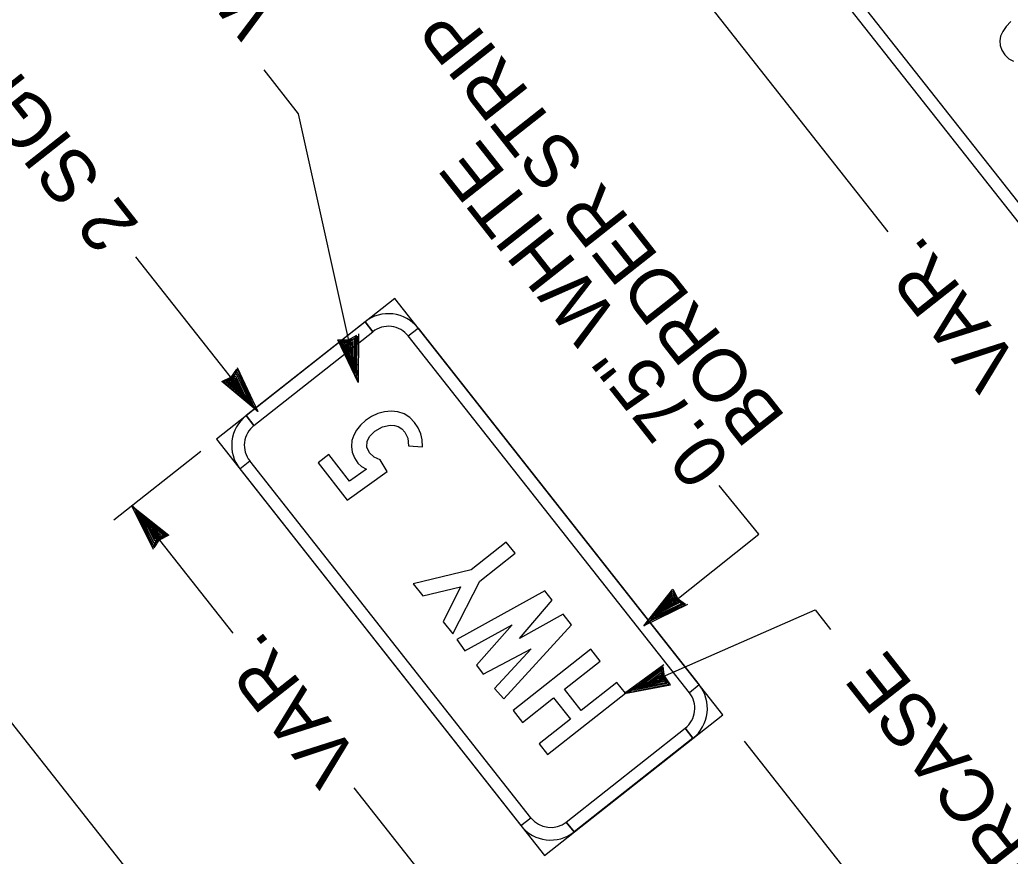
# Model space of a CAD drawing. Extents: x 672438 to 673980, y 1673259 to 1674850.
# Drawn here: x 673647.2 to 673725.7, y 1673361.1 to 1673427.3 of the extents above; entities that cross this region are included whole.
import ezdxf

# ---------------------------------------------------------------- set-up
doc = ezdxf.new("R2010")
doc.units = 0
for name, color, linetype in [('61', 7, 'Continuous'), ('C-ANNO-SYMB', 7, 'Continuous'), ('Level 1', 7, 'Continuous'), ('V-SIGNAL-LOOP', 7, 'Continuous')]:
    doc.layers.add(name, color=color, linetype=linetype)

msp = doc.modelspace()

# ---------------------------------------------------------------- linework, layer by layer
at = {"layer": '61'}
msp.add_lwpolyline([(673683.105, 1673325.233), (673609.575, 1673418.504), (673586.623, 1673400.409), (673660.153, 1673307.138)], close=True, dxfattribs=at)
at = {"layer": 'C-ANNO-SYMB'}
for p, q in [((673688.27, 1673459.545), (673766.277, 1673360.596)), ((673765.205, 1673363.571), (673690.913, 1673457.808)), ((673690.127, 1673457.189), (673764.42, 1673362.952)), ((673676.882, 1673405.27), (673662.746, 1673394.126)), ((673702.884, 1673372.287), (673676.882, 1673405.27)), ((673674.526, 1673403.412), (673665.102, 1673395.983)), ((673674.526, 1673403.412), (673675.145, 1673402.627)), ((673675.145, 1673402.627), (673674.526, 1673403.412)), ((673677.954, 1673402.295), (673678.739, 1673402.914)), ((673677.954, 1673402.295), (673678.739, 1673402.914)), ((673677.954, 1673402.295), (673678.739, 1673402.914)), ((673678.739, 1673402.914), (673701.027, 1673374.643)), ((673665.721, 1673395.198), (673675.145, 1673402.627)), ((673675.145, 1673402.627), (673675.145, 1673402.627)), ((673675.145, 1673402.627), (673675.145, 1673402.627)), ((673700.241, 1673374.024), (673677.954, 1673402.295)), ((673665.721, 1673395.198), (673665.102, 1673395.983)), ((673665.102, 1673395.983), (673665.721, 1673395.198)), ((673662.746, 1673394.126), (673688.748, 1673361.143)), ((673664.603, 1673391.77), (673665.389, 1673392.389)), ((673664.603, 1673391.77), (673665.389, 1673392.389)), ((673665.389, 1673392.389), (673665.389, 1673392.389)), ((673665.389, 1673392.389), (673665.389, 1673392.389)), ((673687.676, 1673364.118), (673665.389, 1673392.389)), ((673664.603, 1673391.77), (673686.891, 1673363.499)), ((673701.027, 1673374.643), (673700.241, 1673374.024)), ((673701.027, 1673374.643), (673700.241, 1673374.024)), ((673700.241, 1673374.024), (673700.241, 1673374.024)), ((673700.241, 1673374.024), (673700.241, 1673374.024)), ((673688.748, 1673361.143), (673702.884, 1673372.287)), ((673702.884, 1673372.287), (673702.884, 1673372.287)), ((673702.884, 1673372.287), (673702.884, 1673372.287)), ((673690.485, 1673363.785), (673699.909, 1673371.215)), ((673699.909, 1673371.215), (673700.528, 1673370.429)), ((673700.528, 1673370.429), (673699.909, 1673371.215)), ((673700.528, 1673370.429), (673691.104, 1673363)), ((673686.891, 1673363.499), (673687.676, 1673364.118)), ((673686.891, 1673363.499), (673687.676, 1673364.118)), ((673691.104, 1673363), (673690.485, 1673363.785)), ((673690.485, 1673363.785), (673690.485, 1673363.785)), ((673690.485, 1673363.785), (673690.485, 1673363.785)), ((673690.485, 1673363.785), (673691.104, 1673363)), ((673691.104, 1673363), (673690.485, 1673363.785))]:
    msp.add_line(p, q, dxfattribs=at)
msp.add_lwpolyline([(673725.719, 1673427.209), (673725.353, 1673426.814), (673725.09, 1673426.424), (673724.92, 1673426.041), (673724.856, 1673425.664), (673724.885, 1673425.293), (673725.017, 1673424.928), (673725.245, 1673424.572), (673725.566, 1673424.255), (673725.933, 1673424.059)], dxfattribs=at)
for points in [[(673679.091, 1673393.514), (673679.058, 1673394.053), (673678.94, 1673394.553), (673678.74, 1673395.015), (673678.458, 1673395.442), (673678.072, 1673395.841), (673677.633, 1673396.126), (673677.139, 1673396.293), (673676.587, 1673396.345), (673676.063, 1673396.296), (673675.551, 1673396.152), (673675.054, 1673395.917), (673674.566, 1673395.587), (673674.169, 1673395.228), (673673.854, 1673394.842), (673673.628, 1673394.434), (673673.487, 1673394.002), (673673.445, 1673393.535), (673673.507, 1673393.081), (673673.68, 1673392.636), (673673.958, 1673392.206), (673674.245, 1673391.943), (673674.644, 1673391.74), (673673.307, 1673390.795), (673671.65, 1673392.897), (673670.804, 1673392.23), (673673.117, 1673389.296), (673676.279, 1673391.547), (673675.717, 1673392.486), (673675.245, 1673392.694), (673674.875, 1673393.03), (673674.661, 1673393.48), (673674.697, 1673393.958), (673674.921, 1673394.367), (673675.299, 1673394.745), (673675.904, 1673395.102), (673676.525, 1673395.236), (673676.863, 1673395.213), (673677.167, 1673395.112), (673677.444, 1673394.936), (673677.686, 1673394.683), (673677.931, 1673394.196), (673677.984, 1673393.598)], [(673679.102, 1673381.704), (673682.102, 1673382.407), (673680.735, 1673379.633), (673681.479, 1673378.689), (673683.639, 1673382.881), (673686.43, 1673385.081), (673685.73, 1673385.97), (673682.938, 1673383.769), (673678.343, 1673382.667)], [(673690.894, 1673379.42), (673690.245, 1673380.243), (673686.775, 1673378.328), (673689.37, 1673381.353), (673688.77, 1673382.114), (673681.818, 1673378.259), (673682.452, 1673377.351), (673686.194, 1673379.413), (673683.354, 1673376.207), (673683.902, 1673375.512), (673687.698, 1673377.507), (673684.799, 1673374.374), (673685.54, 1673373.538)], [(673695.168, 1673373.997), (673694.502, 1673374.842), (673691.675, 1673372.613), (673690.341, 1673374.305), (673693.168, 1673376.534), (673692.426, 1673377.476), (673686.265, 1673372.619), (673687.007, 1673371.677), (673689.478, 1673373.625), (673690.812, 1673371.933), (673688.341, 1673369.985), (673689.007, 1673369.14)]]:
    msp.add_lwpolyline(points, close=True, dxfattribs=at)
for centre, radius, start, end in [((673676.383, 1673401.057), 3, 38.2506, 128.25081), ((673676.383, 1673401.057), 2, 38.2506, 128.25081), ((673666.959, 1673393.627), 3, 128.25054, 218.25075), ((673666.959, 1673393.627), 2, 128.25054, 218.25075), ((673698.671, 1673372.785), 3, 308.25039, 38.2506), ((673698.671, 1673372.785), 2, 308.25039, 38.2506), ((673689.247, 1673365.356), 2, 218.25075, 308.25039), ((673689.247, 1673365.356), 3, 218.25075, 308.25039)]:
    msp.add_arc(centre, radius, start, end, dxfattribs=at)
at = {"layer": 'Level 1'}
for p, q in [((673715.993, 1673410.551), (673681.557, 1673454.232)), ((673666.024, 1673396.3), (673656.366, 1673408.551)), ((673672.765, 1673401.761), (673673.69, 1673402.068)), ((673672.94, 1673401.828), (673673.69, 1673402.068)), ((673673.153, 1673401.953), (673673.871, 1673402.349)), ((673673.224, 1673401.996), (673673.609, 1673402.077)), ((673673.609, 1673402.077), (673673.915, 1673402.278)), ((673673.69, 1673402.068), (673673.686, 1673399.71)), ((673673.69, 1673402.068), (673673.766, 1673399.592)), ((673673.719, 1673402.18), (673673.808, 1673402.146)), ((673673.808, 1673402.146), (673673.845, 1673398.966)), ((673673.915, 1673402.278), (673673.832, 1673399.151)), ((673674.007, 1673402.474), (673673.972, 1673398.616)), ((673672.37, 1673401.975), (673673.224, 1673401.996)), ((673673.972, 1673398.616), (673672.37, 1673401.975)), ((673672.495, 1673401.893), (673673.153, 1673401.953)), ((673673.855, 1673398.915), (673672.495, 1673401.893)), ((673672.646, 1673401.817), (673672.94, 1673401.828)), ((673673.761, 1673399.351), (673672.646, 1673401.817)), ((673673.686, 1673399.71), (673672.765, 1673401.761)), ((673672.903, 1673401.74), (673673.559, 1673401.933)), ((673673.766, 1673399.592), (673672.903, 1673401.74)), ((673673.009, 1673401.627), (673673.453, 1673401.804)), ((673673.571, 1673400.249), (673673.009, 1673401.627)), ((673673.431, 1673401.905), (673673.023, 1673401.685)), ((673673.023, 1673401.685), (673673.484, 1673400.899)), ((673673.107, 1673401.54), (673673.361, 1673401.729)), ((673673.498, 1673400.714), (673673.107, 1673401.54)), ((673673.19, 1673401.533), (673673.284, 1673401.578)), ((673673.379, 1673401.145), (673673.19, 1673401.533)), ((673673.284, 1673401.578), (673673.431, 1673401.905)), ((673673.361, 1673401.729), (673673.379, 1673401.145)), ((673673.453, 1673401.804), (673673.498, 1673400.714)), ((673673.559, 1673401.933), (673673.571, 1673400.249)), ((673673.484, 1673400.899), (673673.463, 1673400.627)), ((673673.463, 1673400.627), (673673.618, 1673400.15)), ((673673.618, 1673400.15), (673673.622, 1673400.633)), ((673664.393, 1673399.796), (673666.024, 1673396.3)), ((673673.876, 1673400.07), (673673.761, 1673399.351)), ((673673.909, 1673399.166), (673673.876, 1673400.07)), ((673663.164, 1673398.682), (673663.932, 1673399.058)), ((673663.312, 1673398.66), (673663.885, 1673398.989)), ((673663.612, 1673398.653), (673664.324, 1673399.319)), ((673663.743, 1673398.786), (673664.324, 1673399.319)), ((673663.747, 1673398.691), (673664.262, 1673399.141)), ((673664.157, 1673399.062), (673663.878, 1673398.692)), ((673663.885, 1673398.989), (673664.371, 1673399.65)), ((673663.89, 1673398.633), (673664.219, 1673398.979)), ((673663.932, 1673399.058), (673664.246, 1673399.293)), ((673664.16, 1673398.704), (673664.157, 1673399.062)), ((673664.219, 1673398.979), (673664.716, 1673398.009)), ((673664.246, 1673399.293), (673664.441, 1673399.603)), ((673664.262, 1673399.141), (673664.977, 1673397.616)), ((673664.371, 1673399.65), (673664.303, 1673399.432)), ((673664.303, 1673399.432), (673664.399, 1673399.438)), ((673664.324, 1673399.319), (673665.307, 1673397.175)), ((673664.324, 1673399.319), (673665.429, 1673397.101)), ((673664.399, 1673399.438), (673665.762, 1673396.566)), ((673664.441, 1673399.603), (673665.673, 1673396.728)), ((673666.024, 1673396.3), (673663.164, 1673398.682)), ((673665.793, 1673396.523), (673663.312, 1673398.66)), ((673663.481, 1673398.654), (673663.743, 1673398.786)), ((673665.524, 1673396.88), (673663.481, 1673398.654)), ((673665.307, 1673397.175), (673663.612, 1673398.653)), ((673665.429, 1673397.101), (673663.747, 1673398.691)), ((673663.878, 1673398.692), (673664.626, 1673398.17)), ((673664.977, 1673397.616), (673663.89, 1673398.633)), ((673664.016, 1673398.595), (673664.168, 1673398.873)), ((673664.716, 1673398.009), (673664.016, 1673398.595)), ((673664.094, 1673398.623), (673664.16, 1673398.704)), ((673664.428, 1673398.35), (673664.094, 1673398.623)), ((673664.168, 1673398.873), (673664.428, 1673398.35)), ((673664.626, 1673398.17), (673664.721, 1673397.915)), ((673661.512, 1673393.139), (673654.608, 1673387.696)), ((673657.755, 1673385.373), (673656.052, 1673388.835)), ((673656.052, 1673388.835), (673658.961, 1673386.513)), ((673664.064, 1673378.741), (673656.086, 1673388.861)), ((673656.411, 1673388.414), (673656.288, 1673388.617)), ((673656.288, 1673388.617), (673658.812, 1673386.531)), ((673657.741, 1673385.731), (673656.32, 1673388.575)), ((673656.32, 1673388.575), (673656.349, 1673388.367)), ((673656.349, 1673388.367), (673656.774, 1673387.568)), ((673657.703, 1673385.565), (673656.411, 1673388.414)), ((673656.774, 1673387.568), (673656.563, 1673388.265)), ((673656.563, 1673388.265), (673658.644, 1673386.534)), ((673657.814, 1673385.852), (673656.663, 1673388.047)), ((673656.663, 1673388.047), (673658.378, 1673386.491)), ((673657.814, 1673385.852), (673656.787, 1673387.975)), ((673656.787, 1673387.975), (673658.512, 1673386.533)), ((673657.388, 1673387.248), (673657.04, 1673387.609)), ((673657.04, 1673387.609), (673657.248, 1673387.174)), ((673657.872, 1673386.031), (673657.126, 1673387.541)), ((673657.126, 1673387.541), (673658.234, 1673386.547)), ((673657.489, 1673386.994), (673657.388, 1673387.248)), ((673657.912, 1673386.193), (673657.395, 1673387.154)), ((673657.395, 1673387.154), (673658.107, 1673386.582)), ((673658.247, 1673386.488), (673657.489, 1673386.994)), ((673657.961, 1673386.301), (673657.69, 1673386.818)), ((673657.69, 1673386.818), (673658.03, 1673386.552)), ((673658.512, 1673386.533), (673657.814, 1673385.852)), ((673658.383, 1673386.396), (673657.814, 1673385.852)), ((673658.378, 1673386.491), (673657.872, 1673386.031)), ((673658.234, 1673386.547), (673657.912, 1673386.193)), ((673658.107, 1673386.582), (673657.961, 1673386.301)), ((673658.03, 1673386.552), (673657.965, 1673386.47)), ((673657.965, 1673386.47), (673657.976, 1673386.112)), ((673657.976, 1673386.112), (673658.247, 1673386.488)), ((673658.961, 1673386.513), (673658.201, 1673386.121)), ((673658.812, 1673386.531), (673658.247, 1673386.191)), ((673658.644, 1673386.534), (673658.383, 1673386.396)), ((673657.891, 1673385.88), (673657.703, 1673385.565)), ((673657.837, 1673385.739), (673657.741, 1673385.731)), ((673658.247, 1673386.191), (673657.774, 1673385.52)), ((673658.201, 1673386.121), (673657.891, 1673385.88)), ((673696.624, 1673379.32), (673698.943, 1673382.23)), ((673696.841, 1673379.556), (673698.925, 1673382.082)), ((673697.192, 1673379.832), (673698.922, 1673381.913)), ((673697.411, 1673379.932), (673698.965, 1673381.648)), ((673697.483, 1673380.056), (673698.924, 1673381.782)), ((673698.922, 1673381.913), (673699.061, 1673381.653)), ((673698.924, 1673381.782), (673699.605, 1673381.084)), ((673698.925, 1673382.082), (673699.266, 1673381.517)), ((673698.943, 1673382.23), (673699.336, 1673381.471)), ((673698.965, 1673381.648), (673699.426, 1673381.142)), ((673699.061, 1673381.653), (673699.605, 1673381.084)), ((673700.084, 1673381.026), (673696.624, 1673379.32)), ((673699.726, 1673381.012), (673696.883, 1673379.588)), ((673699.892, 1673380.973), (673697.044, 1673379.68)), ((673699.605, 1673381.084), (673697.411, 1673379.932)), ((673699.605, 1673381.084), (673697.483, 1673380.056)), ((673697.916, 1673380.395), (673698.91, 1673381.504)), ((673699.426, 1673381.142), (673697.916, 1673380.395)), ((673698.304, 1673380.664), (673698.875, 1673381.377)), ((673699.264, 1673381.182), (673698.304, 1673380.664)), ((673698.969, 1673381.516), (673698.463, 1673380.758)), ((673698.639, 1673380.96), (673698.905, 1673381.3)), ((673699.156, 1673381.231), (673698.639, 1673380.96)), ((673698.875, 1673381.377), (673699.156, 1673381.231)), ((673698.905, 1673381.3), (673698.987, 1673381.235)), ((673698.91, 1673381.504), (673699.264, 1673381.182)), ((673699.345, 1673381.246), (673698.969, 1673381.516)), ((673698.987, 1673381.235), (673699.345, 1673381.246)), ((673699.266, 1673381.517), (673699.937, 1673381.044)), ((673699.336, 1673381.471), (673699.578, 1673381.161)), ((673699.578, 1673381.161), (673699.892, 1673380.973)), ((673699.937, 1673381.044), (673699.718, 1673381.107)), ((673699.718, 1673381.107), (673699.726, 1673381.012)), ((673698.463, 1673380.758), (673698.21, 1673380.657)), ((673698.213, 1673376.231), (673695.093, 1673373.961)), ((673698.034, 1673375.921), (673695.451, 1673374.066)), ((673698.077, 1673376.085), (673695.607, 1673374.166)), ((673698.042, 1673375.78), (673696.001, 1673374.374)), ((673698.042, 1673375.78), (673696.144, 1673374.379)), ((673698.01, 1673375.594), (673696.646, 1673374.605)), ((673697.969, 1673375.432), (673697.065, 1673374.823)), ((673697.888, 1673375.162), (673698.064, 1673375.474)), ((673698.09, 1673374.969), (673697.969, 1673375.432)), ((673698.243, 1673374.951), (673698.01, 1673375.594)), ((673698.115, 1673375.869), (673698.034, 1673375.921)), ((673698.292, 1673375.033), (673698.042, 1673375.78)), ((673698.343, 1673374.852), (673698.042, 1673375.78)), ((673698.064, 1673375.474), (673698.128, 1673375.015)), ((673698.097, 1673375.719), (673698.077, 1673376.085)), ((673698.259, 1673375.361), (673698.097, 1673375.719)), ((673698.161, 1673376.092), (673698.115, 1673375.869)), ((673698.267, 1673375.278), (673698.161, 1673376.092)), ((673698.749, 1673374.66), (673698.259, 1673375.361)), ((673695.093, 1673373.961), (673698.749, 1673374.66)), ((673695.403, 1673374.044), (673698.608, 1673374.713)), ((673695.574, 1673374.236), (673696.322, 1673374.746)), ((673695.811, 1673374.226), (673698.458, 1673374.789)), ((673696.322, 1673374.746), (673695.811, 1673374.226)), ((673696.001, 1673374.374), (673698.243, 1673374.951)), ((673696.144, 1673374.379), (673698.343, 1673374.852)), ((673696.539, 1673374.585), (673696.926, 1673374.874)), ((673697.015, 1673374.743), (673696.539, 1673374.585)), ((673696.646, 1673374.605), (673698.09, 1673374.969)), ((673697.222, 1673374.92), (673697.015, 1673374.743)), ((673697.065, 1673374.823), (673697.961, 1673374.997)), ((673698.128, 1673375.015), (673697.222, 1673374.92)), ((673697.963, 1673375.314), (673697.483, 1673374.982)), ((673697.483, 1673374.982), (673697.907, 1673375.059)), ((673697.907, 1673375.059), (673697.888, 1673375.162)), ((673697.961, 1673374.997), (673697.963, 1673375.314)), ((673698.608, 1673374.713), (673698.267, 1673375.278)), ((673698.458, 1673374.789), (673698.292, 1673375.033)), ((673695.607, 1673374.166), (673695.403, 1673374.044)), ((673695.451, 1673374.066), (673695.574, 1673374.236)), ((673704.586, 1673370.183), (673713.415, 1673358.983)), ((673682.047, 1673355.86), (673673.667, 1673366.49))]:
    msp.add_line(p, q, dxfattribs=at)
for points in [[(673673.972, 1673398.616), (673669.265, 1673419.895), (673666.519, 1673423.378)], [(673696.624, 1673379.32), (673705.736, 1673386.581), (673702.599, 1673390.437)], [(673695.093, 1673373.961), (673710.201, 1673380.598), (673711.424, 1673379.047)]]:
    msp.add_lwpolyline(points, dxfattribs=at)
at = {"layer": 'V-SIGNAL-LOOP'}
msp.add_lwpolyline([(673706.6, 1673379.419), (673706.6, 1673379.419), (673706.6, 1673379.419)], dxfattribs=at)

# ---------------------------------------------------------------- texts
at = {"layer": 'Level 1'}
for s, p in [('WHITE TEXT ON', (673668.031, 1673428.122)), ('2 SIGNS REQUIRED', (673656.723, 1673411.09)), ('BORDER STRIP', (673707.963, 1673395.834)), ('0.75" WHITE ', (673703.669, 1673392.449)), ('VAR.', (673726.546, 1673400.145)), ('VAR.', (673674.24, 1673368.813)), ('8" UPPERCASE', (673741.345, 1673345.099))]:
    msp.add_text(s, height=4.2, rotation=128.25054, dxfattribs=at).set_placement(p)

doc.saveas('drawing.dxf')
